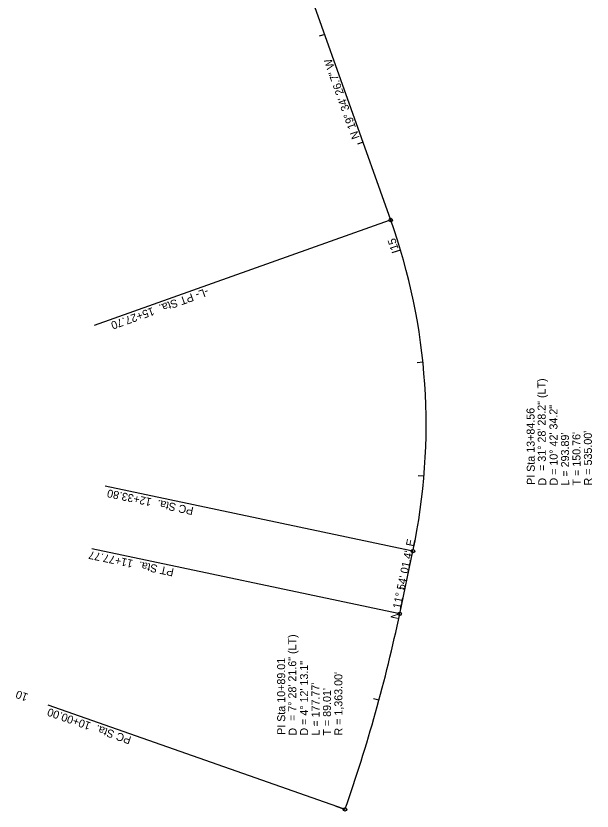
# Model space of a CAD drawing. Extents: x 1373164 to 1374172, y 550391 to 553180.
# Drawn here: x 1373518 to 1374022, y 550391 to 551086 of the extents above; entities that cross this region are included whole.
import ezdxf

# ---------------------------------------------------------------- set-up
doc = ezdxf.new("R2010")
doc.units = 0
for name, color, linetype in [('Exist Building Cogo Point CELL', 7, 'Continuous'), ('Exist Roads EOP Other Cogo Comment', 7, 'Continuous'), ('Exist Roads EOP Other Cogo Elevation', 7, 'Continuous'), ('Exist Structure Minor Pipes RCP 18 Inch Cogo Comment', 7, 'Continuous'), ('Exist Structure Minor Pipes RCP 18 Inch Cogo Elevation', 7, 'Continuous'), ('Exist Structure Minor Pipes RCP 18 Inch Cogo Number', 7, 'Continuous'), ('Exist Structure Minor Pipes RCP 18 Inch Cogo Point CELL', 7, 'Continuous'), ('Exist Utilities Sanitary Sewer Manhole Cogo Elevation', 7, 'Continuous')]:
    doc.layers.add(name, color=color, linetype=linetype)

msp = doc.modelspace()

# ---------------------------------------------------------------- linework, layer by layer
at = {"layer": 'Exist Building Cogo Point CELL'}
for p, q in [((1373788, 551069.96), (1373783.29, 551068.28)), ((1373821.51, 550975.74), (1373816.8, 550974.06)), ((1373873.82, 550783.35), (1373868.84, 550782.84)), ((1373874.76, 550683.5), (1373869.78, 550683.92)), ((1373858.18, 550584.97), (1373853.29, 550586.01)), ((1373835.4, 550487.62), (1373830.57, 550488.93))]:
    msp.add_line(p, q, dxfattribs=at)
at = {"layer": 'Exist Roads EOP Other Cogo Elevation'}
for p, q in [((1373845.73, 550907.61), (1373775.97, 551103.81)), ((1373853.59, 550563.22), (1373865.15, 550618.05))]:
    msp.add_line(p, q, dxfattribs=at)
for centre, radius, start, end in [((1373341.65, 550728.38), 535, 348.0996, 19.57409), ((1372519.89, 550844.28), 1363, 340.62693, 348.0996)]:
    msp.add_arc(centre, radius, start, end, dxfattribs=at)
at = {"layer": 'Exist Structure Minor Pipes RCP 18 Inch Cogo Comment'}
for p, q in [((1373854.33, 550881.29), (1373846.66, 550879)), ((1373805.71, 550392.15), (1373798.17, 550394.81))]:
    msp.add_line(p, q, dxfattribs=at)
at = {"layer": 'Exist Structure Minor Pipes RCP 18 Inch Cogo Number'}
for p, q in [((1373844.32, 550907.11), (1373586.62, 550815.48)), ((1373863.68, 550618.36), (1373596.06, 550674.76)), ((1373852.13, 550563.53), (1373584.51, 550619.93)), ((1373804.3, 550392.65), (1373546.29, 550483.38))]:
    msp.add_line(p, q, dxfattribs=at)
for centre in [(1373845.73, 550907.61), (1373865.15, 550618.05), (1373853.59, 550563.22), (1373805.71, 550392.15)]:
    msp.add_circle(centre, 1.5, dxfattribs=at)
at = {"layer": 'Exist Utilities Sanitary Sewer Manhole Cogo Elevation'}
msp.add_line((1373805.71, 550392.15), (1373805.71, 550392.15), dxfattribs=at)

# ---------------------------------------------------------------- texts
at = {"layer": 'Exist Roads EOP Other Cogo Comment'}
for s, rotation, p in [('N 19%%d 34\' 26.7" W', 109.57409, (1373818.56, 550979.75)), ('N 11%%d 54\' 01.4" E', 78.0996, (1373852.28, 550557.95))]:
    msp.add_text(s, height=7, rotation=rotation, dxfattribs=at).set_placement(p)
at = {"layer": 'Exist Structure Minor Pipes RCP 18 Inch Cogo Elevation'}
for s, rotation, p in [('15', 107.60675, (1373852.62, 550882.38)), ('10', 160.62693, (1373529.39, 550493.03))]:
    msp.add_text(s, height=7, rotation=rotation, dxfattribs=at).set_placement(p)
at = {"layer": 'Exist Structure Minor Pipes RCP 18 Inch Cogo Number'}
for s, rotation, p in [('-L- PT Sta.  15+27.70', 199.57409, (1373685.12, 550848.38)), ('PC Sta.  12+33.80', 168.0996, (1373673.84, 550656.33)), ('PT Sta.  11+77.77', 168.0996, (1373656.68, 550602.67)), ('PC Sta.  10+00.00', 160.62693, (1373619.55, 550455.49))]:
    msp.add_text(s, height=7, rotation=rotation, dxfattribs=at).set_placement(p)
at = {"layer": 'Exist Structure Minor Pipes RCP 18 Inch Cogo Point CELL'}
for s, rotation, p in [('= 31%%d 28\' 28.2" (LT)', 90.26354, (1373981.31, 550688.18)), ('D = 10%%d 42\' 34.2"', 90.26354, (1373991.66, 550675.38)), ('PI Sta 13+84.56', 90.26354, (1373971.66, 550675.96)), ("R = 535.00'", 90.26354, (1374021.66, 550675.52)), ("L = 293.89'", 90.26354, (1374001.66, 550675.43)), ("T = 150.76'", 90.26354, (1374011.66, 550675.47)), ('D', 90.26354, (1373981.66, 550675.33)), ('= 7%%d 28\' 21.6" (LT)', 90.07288, (1373763.2, 550469.51)), ('PI Sta 10+89.01', 90.07288, (1373753.51, 550457.32)), ('D = 4%%d 12\' 13.1"', 90.07288, (1373773.51, 550456.67)), ("R = 1,363.00'", 90.07288, (1373803.51, 550456.71)), ("L = 177.77'", 90.07288, (1373783.51, 550456.68)), ("T = 89.01'", 90.07288, (1373793.51, 550456.7)), ('D', 90.07288, (1373763.51, 550456.66))]:
    msp.add_text(s, height=7, rotation=rotation, dxfattribs=at).set_placement(p)

doc.saveas('drawing.dxf')
